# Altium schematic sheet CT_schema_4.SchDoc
size 366 x 245 mm
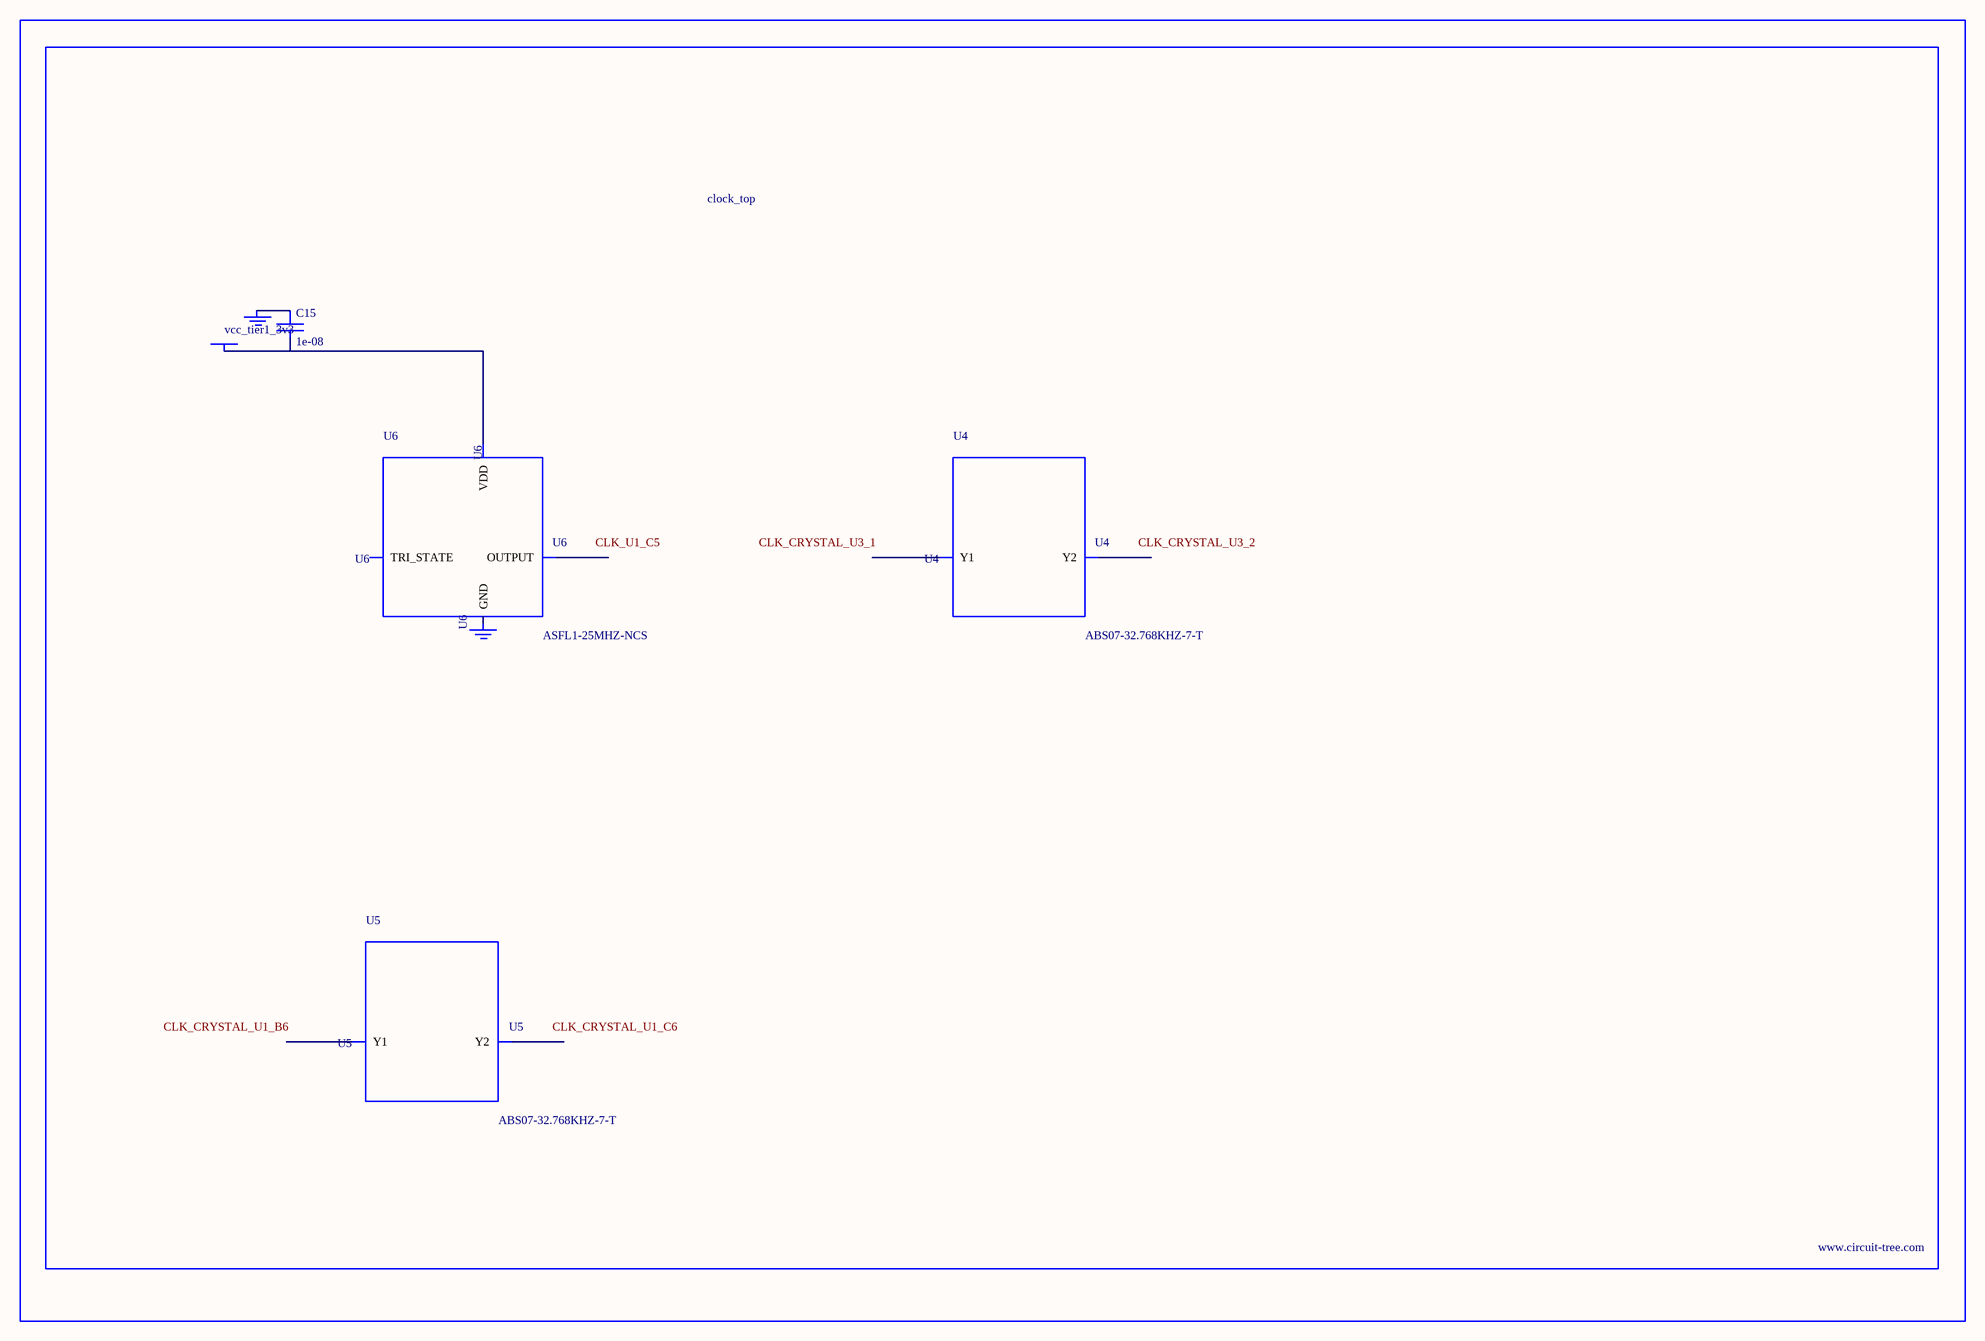
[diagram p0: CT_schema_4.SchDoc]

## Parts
BORDER3  (no value)
C15  1e-08  [C0402]
GND_INSTANCE_3_0  (no value)
GND_INSTANCE_3_1  (no value)
POWER_INSTANCE_3_0  vcc_tier1_3v3
U4  ABS07-32.768KHZ-7-T  [ABS07-32.768KHZ-7-T]
U5  ABS07-32.768KHZ-7-T  [ABS07-32.768KHZ-7-T]
U6  ASFL1-25MHZ-NCS  [ASFL1]

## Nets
NetC15_1: C15.1 GND_INSTANCE_3_0.0(GND)
NetC15_2: C15.2 POWER_INSTANCE_3_0.0(PWR) U6.4(VDD)

Not connected (* = marked no-connect by the designer): GND_INSTANCE_3_1 0(GND); U4 1(Y1) 2(Y2); U5 1(Y1) 2(Y2); U6 1(TRI_STATE) 2(GND) 3(OUTPUT)

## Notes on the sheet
- Labels drawn without touching a wire or pin: CLK_CRYSTAL_U1_B6, CLK_CRYSTAL_U1_C6, CLK_CRYSTAL_U3_1, CLK_CRYSTAL_U3_2, CLK_U1_C5

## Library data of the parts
BORDER3 = BORDER_PAGE3
C15 = C0402C103K3RAC
GND_INSTANCE_3_0 GND_INSTANCE_3_1 = GND
POWER_INSTANCE_3_0 = PWR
